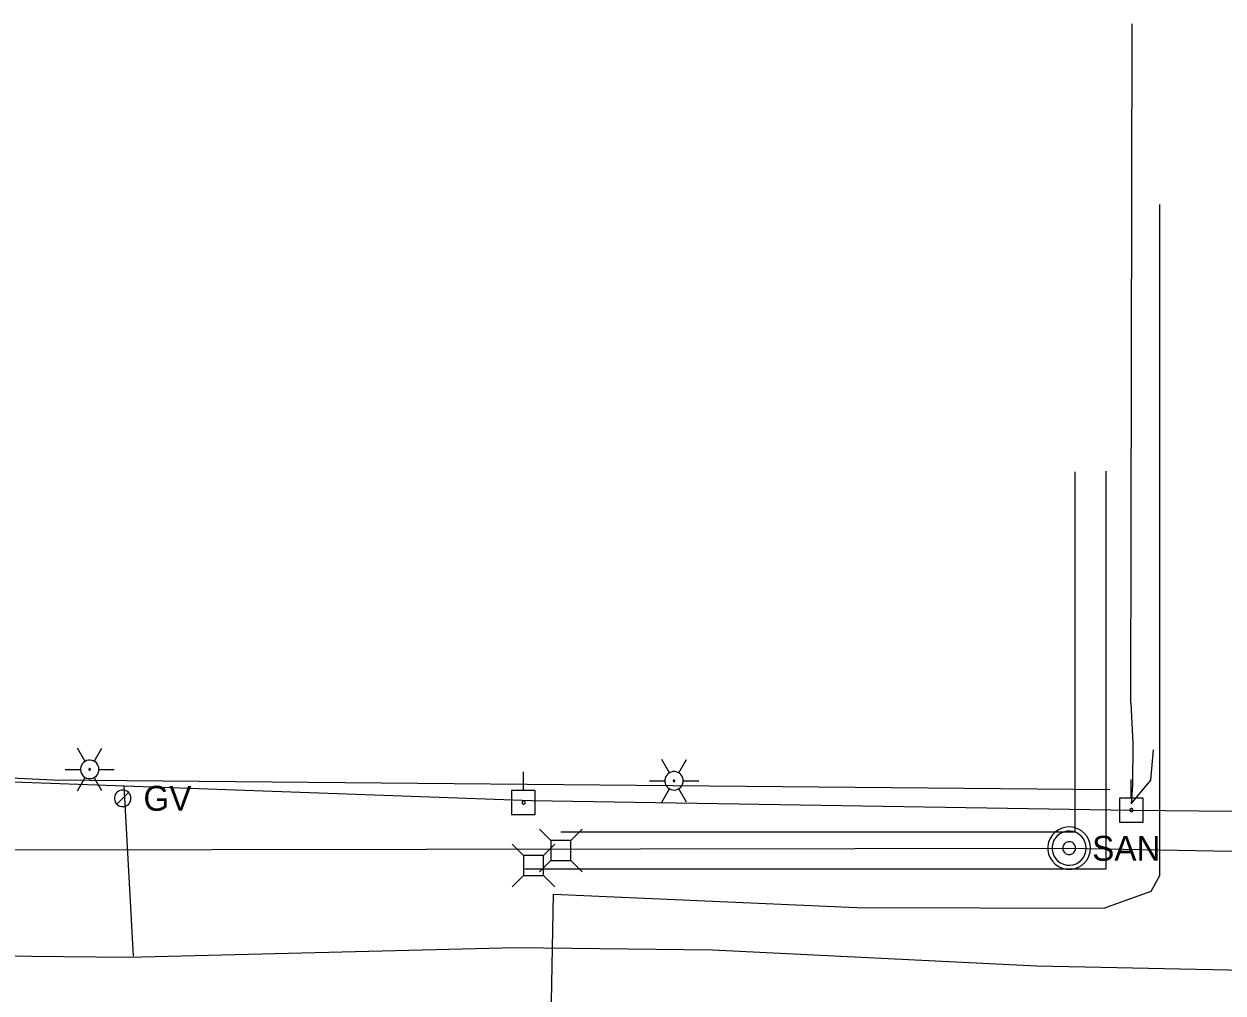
# Model space of a CAD drawing. Extents: x 596028 to 606371, y 330010 to 403088.
# Drawn here: x 604575.9 to 604761.5, y 349952.8 to 350102.8 of the extents above; entities that cross this region are included whole.
import ezdxf

# ---------------------------------------------------------------- set-up
doc = ezdxf.new("R2010")
doc.units = 0
for name, color, linetype in [('E_LTG', 7, 'Continuous'), ('E_UTL_EPowerPole', 7, 'Continuous'), ('E_UTL_G', 7, 'Continuous'), ('E_UTL_G_UG', 7, 'Continuous'), ('E_UTL_Overhead', 7, 'Continuous'), ('E_UTL_SAN_MH', 7, 'Continuous'), ('E_UTL_SAN_UG', 7, 'Continuous'), ('E_UTL_T', 7, 'Continuous'), ('E_UTL_T_UG', 7, 'Continuous'), ('E_UTL_TV_UG', 7, 'Continuous')]:
    doc.layers.add(name, color=color, linetype=linetype)

# ---------------------------------------------------------------- blocks, each defined once
blk = doc.blocks.new('ACAD_PROXY_ENTITY_15')
at = {"layer": 'E_LTG'}
for points in [[(1843663.8, 1030159.59), (1843660.17, 1030165.87)], [(1843668.16, 1030159.59), (1843671.79, 1030165.87)], [(1843654.37, 1030155.82), (1843661.62, 1030155.82)], [(1843670.34, 1030155.82), (1843670.26, 1030156.64), (1843670.02, 1030157.44), (1843669.64, 1030158.17), (1843669.13, 1030158.82), (1843668.51, 1030159.36), (1843667.79, 1030159.78), (1843667.01, 1030160.05), (1843666.19, 1030160.17), (1843665.36, 1030160.13), (1843664.56, 1030159.93), (1843663.8, 1030159.59), (1843663.13, 1030159.11), (1843662.56, 1030158.51), (1843662.11, 1030157.81), (1843661.8, 1030157.04), (1843661.64, 1030156.23), (1843661.64, 1030155.4), (1843661.8, 1030154.59), (1843662.11, 1030153.82), (1843662.56, 1030153.12), (1843663.13, 1030152.52), (1843663.8, 1030152.04), (1843664.56, 1030151.7), (1843665.36, 1030151.51), (1843666.19, 1030151.47), (1843667.01, 1030151.58), (1843667.79, 1030151.85), (1843668.51, 1030152.27), (1843669.13, 1030152.81), (1843669.64, 1030153.46), (1843670.02, 1030154.2), (1843670.26, 1030154.99), (1843670.34, 1030155.82)], [(1843670.34, 1030155.82), (1843670.26, 1030156.64), (1843670.02, 1030157.44), (1843669.64, 1030158.17), (1843669.13, 1030158.82), (1843668.51, 1030159.36), (1843667.79, 1030159.78), (1843667.01, 1030160.05), (1843666.19, 1030160.17), (1843665.36, 1030160.13), (1843664.56, 1030159.93), (1843663.8, 1030159.59), (1843663.13, 1030159.11), (1843662.56, 1030158.51), (1843662.11, 1030157.81), (1843661.8, 1030157.04), (1843661.64, 1030156.23), (1843661.64, 1030155.4), (1843661.8, 1030154.59), (1843662.11, 1030153.82), (1843662.56, 1030153.12), (1843663.13, 1030152.52), (1843663.8, 1030152.04), (1843664.56, 1030151.7), (1843665.36, 1030151.51), (1843666.19, 1030151.47), (1843667.01, 1030151.58), (1843667.79, 1030151.85), (1843668.51, 1030152.27), (1843669.13, 1030152.81), (1843669.64, 1030153.46), (1843670.02, 1030154.2), (1843670.26, 1030154.99), (1843670.34, 1030155.82)], [(1843670.34, 1030155.82), (1843670.26, 1030156.64), (1843670.02, 1030157.44), (1843669.64, 1030158.17), (1843669.13, 1030158.82), (1843668.51, 1030159.36), (1843667.79, 1030159.78), (1843667.01, 1030160.05), (1843666.19, 1030160.17), (1843665.36, 1030160.13), (1843664.56, 1030159.93), (1843663.8, 1030159.59), (1843663.13, 1030159.11), (1843662.56, 1030158.51), (1843662.11, 1030157.81), (1843661.8, 1030157.04), (1843661.64, 1030156.23), (1843661.64, 1030155.4), (1843661.8, 1030154.59), (1843662.11, 1030153.82), (1843662.56, 1030153.12), (1843663.13, 1030152.52), (1843663.8, 1030152.04), (1843664.56, 1030151.7), (1843665.36, 1030151.51), (1843666.19, 1030151.47), (1843667.01, 1030151.58), (1843667.79, 1030151.85), (1843668.51, 1030152.27), (1843669.13, 1030152.81), (1843669.64, 1030153.46), (1843670.02, 1030154.2), (1843670.26, 1030154.99), (1843670.34, 1030155.82)], [(1843666.34, 1030155.82), (1843666.34, 1030155.88), (1843666.32, 1030155.95), (1843666.29, 1030156.01), (1843666.24, 1030156.07), (1843666.19, 1030156.11), (1843666.13, 1030156.15), (1843666.07, 1030156.17), (1843666, 1030156.18), (1843665.93, 1030156.18), (1843665.86, 1030156.16), (1843665.8, 1030156.13), (1843665.74, 1030156.09), (1843665.69, 1030156.04), (1843665.66, 1030155.98), (1843665.63, 1030155.92), (1843665.62, 1030155.85), (1843665.62, 1030155.78), (1843665.63, 1030155.71), (1843665.66, 1030155.65), (1843665.69, 1030155.59), (1843665.74, 1030155.54), (1843665.8, 1030155.5), (1843665.86, 1030155.47), (1843665.93, 1030155.46), (1843666, 1030155.45), (1843666.07, 1030155.46), (1843666.13, 1030155.49), (1843666.19, 1030155.52), (1843666.24, 1030155.57), (1843666.29, 1030155.62), (1843666.32, 1030155.68), (1843666.34, 1030155.75), (1843666.34, 1030155.82)], [(1843670.34, 1030155.82), (1843677.59, 1030155.82)], [(1843660.17, 1030145.76), (1843663.8, 1030152.04)], [(1843671.79, 1030145.76), (1843668.16, 1030152.04)]]:
    blk.add_lwpolyline(points, dxfattribs=at)

msp = doc.modelspace()

# ---------------------------------------------------------------- linework, layer by layer
at = {"layer": 'E_UTL_EPowerPole'}
for points in [[(604653.23, 349984.15), (604653.23, 349987.06)], [(604747.3, 349982.98), (604747.3, 349985.89)], [(604655.08, 349984.15), (604651.39, 349984.15)], [(604651.39, 349984.15), (604651.39, 349980.46)], [(604655.08, 349980.46), (604655.08, 349984.15)], [(604749.15, 349982.98), (604745.46, 349982.98)], [(604745.46, 349982.98), (604745.46, 349979.29)], [(604749.15, 349979.29), (604749.15, 349982.98)], [(604653.5, 349982.31), (604653.5, 349982.35), (604653.49, 349982.4), (604653.46, 349982.44), (604653.44, 349982.47), (604653.4, 349982.5), (604653.36, 349982.52), (604653.32, 349982.54), (604653.28, 349982.55), (604653.23, 349982.54), (604653.19, 349982.53), (604653.14, 349982.51), (604653.11, 349982.49), (604653.08, 349982.46), (604653.05, 349982.42), (604653.04, 349982.38), (604653.03, 349982.33), (604653.03, 349982.29), (604653.04, 349982.24), (604653.05, 349982.2), (604653.08, 349982.16), (604653.11, 349982.13), (604653.14, 349982.1), (604653.19, 349982.08), (604653.23, 349982.07), (604653.28, 349982.07), (604653.32, 349982.08), (604653.36, 349982.09), (604653.4, 349982.11), (604653.44, 349982.14), (604653.46, 349982.18), (604653.49, 349982.22), (604653.5, 349982.26), (604653.5, 349982.31)], [(604747.57, 349981.14), (604747.57, 349981.19), (604747.56, 349981.23), (604747.53, 349981.27), (604747.51, 349981.31), (604747.47, 349981.34), (604747.43, 349981.36), (604747.39, 349981.37), (604747.35, 349981.38), (604747.3, 349981.38), (604747.26, 349981.37), (604747.21, 349981.35), (604747.18, 349981.32), (604747.15, 349981.29), (604747.12, 349981.25), (604747.11, 349981.21), (604747.1, 349981.16), (604747.1, 349981.12), (604747.11, 349981.07), (604747.12, 349981.03), (604747.15, 349980.99), (604747.18, 349980.96), (604747.21, 349980.93), (604747.26, 349980.92), (604747.3, 349980.9), (604747.35, 349980.9), (604747.39, 349980.91), (604747.43, 349980.92), (604747.47, 349980.95), (604747.51, 349980.98), (604747.53, 349981.01), (604747.56, 349981.05), (604747.57, 349981.1), (604747.57, 349981.14)], [(604651.39, 349980.46), (604655.08, 349980.46)], [(604745.46, 349979.29), (604749.15, 349979.29)]]:
    msp.add_lwpolyline(points, dxfattribs=at)
at = {"layer": 'E_UTL_G'}
for points in [[(604592.5, 349982.96), (604592.48, 349983.21), (604592.41, 349983.44), (604592.3, 349983.66), (604592.15, 349983.85), (604591.96, 349984.01), (604591.75, 349984.13), (604591.52, 349984.21), (604591.28, 349984.24), (604591.04, 349984.23), (604590.8, 349984.18), (604590.58, 349984.07), (604590.38, 349983.93), (604590.21, 349983.76), (604590.08, 349983.55), (604589.99, 349983.32), (604589.94, 349983.09), (604589.94, 349982.84), (604589.99, 349982.6), (604590.08, 349982.37), (604590.21, 349982.17), (604590.38, 349981.99), (604590.58, 349981.85), (604590.8, 349981.75), (604591.04, 349981.69), (604591.28, 349981.68), (604591.52, 349981.72), (604591.75, 349981.8), (604591.96, 349981.92), (604592.15, 349982.08), (604592.3, 349982.27), (604592.41, 349982.49), (604592.48, 349982.72), (604592.5, 349982.96)], [(604590.31, 349982.06), (604592.13, 349983.87)]]:
    msp.add_lwpolyline(points, dxfattribs=at)
at = {"layer": 'E_UTL_G_UG'}
for points in [[(604252.85, 349997.07), (604335.69, 349990.44), (604349.27, 349988.73), (604376.12, 349984.81), (604411.24, 349982.02), (604444.79, 349980.04), (604487.55, 349978.81), (604487.8, 349967.33), (604488.65, 349961.03), (604506.03, 349960.73), (604527.14, 349959.03), (604592.13, 349958.39), (604651.99, 349959.87), (604682.48, 349959.49), (604732.67, 349957.01), (604787.08, 349955.9), (604797.56, 349955.68)], [(604592.89, 349958.51), (604591.45, 349984.89)]]:
    msp.add_lwpolyline(points, dxfattribs=at)
at = {"layer": 'E_UTL_Overhead'}
msp.add_lwpolyline([(603181.28, 350035.1), (603329.32, 350032.13), (603487.19, 350051.84), (603697.5, 350053.11), (603794.73, 350045.64), (603986.8, 350030.72), (604135.55, 350019.1), (604355.8, 350001.36), (604456.04, 349993.24), (604557.11, 349986.14), (604654.49, 349982.64), (604747.33, 349981.14), (604855.96, 349980.06), (604969.76, 349979.4), (605156.33, 349975.18)], dxfattribs=at)
at = {"layer": 'E_UTL_SAN_MH'}
for points in [[(604740.98, 349975.25), (604740.92, 349975.87), (604740.75, 349976.47), (604740.46, 349977.03), (604740.07, 349977.52), (604739.6, 349977.93), (604739.05, 349978.25), (604738.46, 349978.45), (604737.84, 349978.54), (604737.21, 349978.51), (604736.6, 349978.36), (604736.03, 349978.1), (604735.52, 349977.74), (604735.09, 349977.29), (604734.75, 349976.76), (604734.52, 349976.18), (604734.4, 349975.56), (604734.4, 349974.93), (604734.52, 349974.32), (604734.75, 349973.73), (604735.09, 349973.21), (604735.52, 349972.75), (604736.03, 349972.39), (604736.6, 349972.13), (604737.21, 349971.98), (604737.84, 349971.95), (604738.46, 349972.04), (604739.05, 349972.24), (604739.6, 349972.56), (604740.07, 349972.97), (604740.46, 349973.46), (604740.75, 349974.02), (604740.92, 349974.62), (604740.98, 349975.25)], [(604740.32, 349975.25), (604740.28, 349975.75), (604740.13, 349976.23), (604739.9, 349976.67), (604739.59, 349977.07), (604739.21, 349977.4), (604738.78, 349977.65), (604738.31, 349977.81), (604737.81, 349977.88), (604737.31, 349977.86), (604736.82, 349977.74), (604736.36, 349977.53), (604735.95, 349977.24), (604735.61, 349976.88), (604735.34, 349976.46), (604735.15, 349975.99), (604735.06, 349975.5), (604735.06, 349974.99), (604735.15, 349974.5), (604735.34, 349974.04), (604735.61, 349973.61), (604735.95, 349973.25), (604736.36, 349972.96), (604736.82, 349972.75), (604737.31, 349972.63), (604737.81, 349972.61), (604738.31, 349972.68), (604738.78, 349972.84), (604739.21, 349973.1), (604739.59, 349973.42), (604739.9, 349973.82), (604740.13, 349974.26), (604740.28, 349974.75), (604740.32, 349975.25)], [(604738.67, 349975.25), (604738.66, 349975.43), (604738.6, 349975.61), (604738.52, 349975.78), (604738.4, 349975.93), (604738.26, 349976.05), (604738.09, 349976.15), (604737.92, 349976.21), (604737.73, 349976.23), (604737.54, 349976.23), (604737.36, 349976.18), (604737.19, 349976.1), (604737.03, 349975.99), (604736.91, 349975.86), (604736.8, 349975.7), (604736.73, 349975.52), (604736.7, 349975.34), (604736.7, 349975.15), (604736.73, 349974.97), (604736.8, 349974.79), (604736.91, 349974.63), (604737.03, 349974.5), (604737.19, 349974.39), (604737.36, 349974.31), (604737.54, 349974.27), (604737.73, 349974.26), (604737.92, 349974.28), (604738.09, 349974.35), (604738.26, 349974.44), (604738.4, 349974.56), (604738.52, 349974.71), (604738.6, 349974.88), (604738.66, 349975.06), (604738.67, 349975.25)]]:
    msp.add_lwpolyline(points, dxfattribs=at)
at = {"layer": 'E_UTL_SAN_UG'}
for p, q in [((604407.98, 349974.7), (604737.68, 349975.25)), ((604737.68, 349975.25), (605035.81, 349969.84))]:
    msp.add_line(p, q, dxfattribs=at)
at = {"layer": 'E_UTL_T'}
for points in [[(604657.48, 349976.41), (604655.73, 349978.16)], [(604660.58, 349976.41), (604662.33, 349978.16)], [(604653.25, 349974.13), (604651.5, 349975.88)], [(604656.35, 349974.13), (604658.1, 349975.88)], [(604660.58, 349976.41), (604657.48, 349976.41)], [(604657.48, 349976.41), (604657.48, 349973.31)], [(604660.58, 349973.31), (604660.58, 349976.41)], [(604656.35, 349974.13), (604653.25, 349974.13)], [(604653.25, 349974.13), (604653.25, 349971.03)], [(604657.48, 349973.31), (604655.73, 349971.56)], [(604656.35, 349971.03), (604656.35, 349974.13)], [(604657.48, 349973.31), (604660.58, 349973.31)], [(604660.58, 349973.31), (604662.33, 349971.56)], [(604653.25, 349971.03), (604651.5, 349969.28)], [(604653.25, 349971.03), (604656.35, 349971.03)], [(604656.35, 349971.03), (604658.1, 349969.28)]]:
    msp.add_lwpolyline(points, dxfattribs=at)
at = {"layer": 'E_UTL_T_UG'}
msp.add_line((604580.52, 349985.83), (604743.99, 349984.3), dxfattribs=at)
for points in [[(604743.07, 349965.98), (604750.38, 349968.61), (604751.75, 349971), (604751.75, 350074.87)], [(604653.44, 349972.05), (604743.4, 349972.05), (604743.4, 350033.62)], [(604659.03, 349977.77), (604738.6, 349977.77), (604738.6, 350033.49)], [(604353.29, 350001.85), (604451.46, 349993.55), (604554.09, 349987.33), (604556.31, 349986.95), (604580.52, 349985.83)], [(604648.72, 349878.82), (604655.38, 349882.89), (604657.44, 349895.7), (604658.3, 349920.9), (604657.2, 349932.04), (604657.87, 349968.11)], [(604657.87, 349968.11), (604704.82, 349966.05), (604743.07, 349965.98)]]:
    msp.add_lwpolyline(points, dxfattribs=at)
at = {"layer": 'E_UTL_TV_UG'}
msp.add_line((604747.25, 349997.67), (604747.44, 350102.82), dxfattribs=at)
msp.add_lwpolyline([(604747.25, 349997.67), (604747.56, 349991.43), (604747.48, 349984.99), (604747.31, 349982.1), (604750.33, 349985.77), (604750.75, 349990.46)], dxfattribs=at)

# ---------------------------------------------------------------- block references
at = {"layer": 'E_LTG', "xscale": 0.32808333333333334, "yscale": 0.32808333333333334}
for p in [(-289.97, 12010.49), (-199.53, 12008.72)]:
    msp.add_blockref('ACAD_PROXY_ENTITY_15', p, dxfattribs=at)

# ---------------------------------------------------------------- texts
at = {"layer": 'E_UTL_G'}
msp.add_text('GV', height=3.85, dxfattribs=at).set_placement((604594.43, 349981.04))
at = {"layer": 'E_UTL_SAN_MH'}
msp.add_text('SAN', height=3.849, dxfattribs=at).set_placement((604741.25, 349973.3))

doc.saveas('drawing.dxf')
